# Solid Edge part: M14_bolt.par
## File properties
Title: 62102 HEXAGON HEAD BOLTS PARTIAL THREAD - 6210214X45
Author: TraceParts S.A.
Template: Iso Metric Part.par
Last saved by: Nimesh.N
Revision: 19
Application: TraceParts
Company: TraceParts S.A.
Density: 7833.000 kg/m^3
Accuracy: 0.990
REFERENCE: 6210214X45
STANDARD2: (similar ISO 4014)
STANDARD1: DIN 931
SUPPLIER: Acton
DESIGN: 62102 HEXAGON HEAD BOLTS PARTIAL THREAD - 6210214X45
MATERIAL: Inox A2
TraceParts.PartNumber: 10-27012020-095198
TraceParts.InstanceId: 10-27012020-0951984WV911PX7NTU5D7LYGBWOCZ85
TraceParts.PartLanguage: en
TraceParts.PartTitle: 62102 HEXAGON HEAD BOLTS PARTIAL THREAD
TRACEPARTS: TRACEPARTS
TraceParts.PartVersion: 1.1.1
Username: Nimesh.N
Material: Steel
Face Style: Steel
Fill Style: ANSI32(Steel)
Virtual Style: Machined steel
Grouping: Metals\Steel
LibraryName: Materials
Coef. of Thermal Exp: 1.3e-05
Thermal Conductivity: 32.0
Specific Heat: 481.0
Modulus of Elasticity: 199947953000.0
Poisson's Ratio: 0.29
Yield Stress: 262000766.0
Ultimate Stress: 358527364.0
Elongation: 0.0
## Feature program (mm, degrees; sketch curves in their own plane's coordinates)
body "unnamed Body 1"
thread "unnamed Thread 1"
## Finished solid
Body 1: solid body, 20 faces, 36 edges, 24 vertices.
  Faces by surface: plane 10, cone 7, cylinder 2, torus 1
  Edges by curve: circle 12, curve on surface 12, line 12
Bounding box of the edges (mm; curved faces can reach further): 53.800 x 25.403 x 22.000, from (-8.8, -12.7017, -11) to (45, 12.7017, 11).
Cylindrical faces by radius (mm): R7 x1, R9.685 x1
Conical faces (half-angle, radius in mm at the cone's reference point): 55 deg R7 x1, 70 deg R11 x6
Toroidal faces (ring radius, tube radius in mm): R7.6 r0.6 x1
Planar faces by outward normal: +x 3, +z 1, -x 1, -z 1, oblique 4
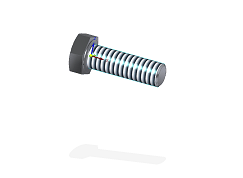
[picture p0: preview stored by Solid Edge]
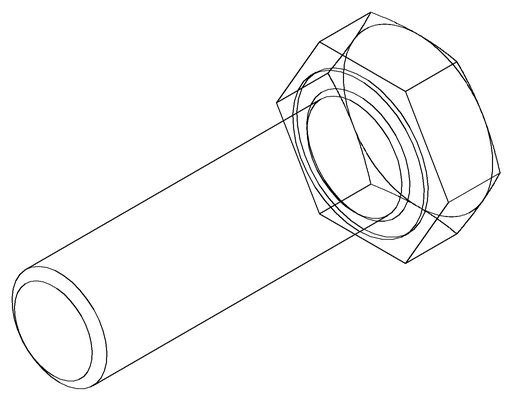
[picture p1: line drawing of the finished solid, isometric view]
